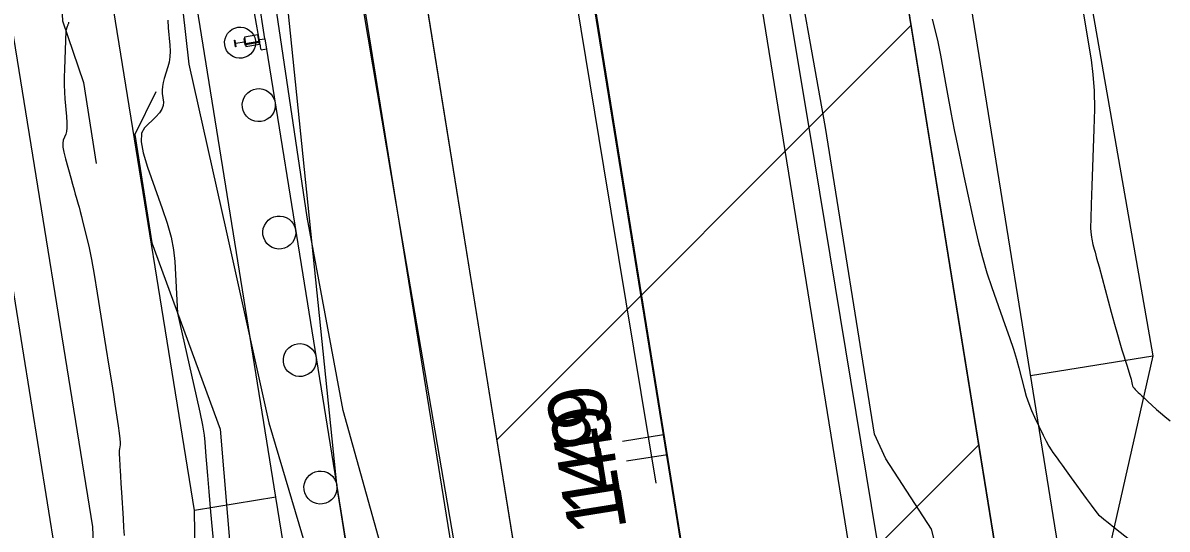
# Model space of a CAD drawing. Extents: x 2030588 to 2035216, y 462285 to 465007.
# Drawn here: x 2031209.2 to 2031264.6, y 464376.7 to 464401.2 of the extents above; entities that cross this region are included whole.
import ezdxf

# ---------------------------------------------------------------- set-up
doc = ezdxf.new("R2010")
doc.units = 0
for name, color, linetype in [('DT_P_Pavement_Surface', 7, 'Continuous'), ('DT_P_Slope_Break_Line', 7, 'Continuous'), ('DT_X_Contour_Minor', 7, 'Continuous'), ('GE_X_Alignment', 7, 'Continuous'), ('GE_X_Alignment_100_Stations', 7, 'Continuous'), ('MD_P_CONST_LIMITS', 7, 'Continuous'), ('MT_P_Temp_Road', 7, 'Continuous'), ('PV_P_EOP', 7, 'Continuous'), ('PV_P_Shoulder', 7, 'Continuous'), ('PV_X_COP', 7, 'Continuous'), ('PV_X_EOP', 7, 'Continuous'), ('PV_X_Shoulder_Aggregate', 7, 'Continuous'), ('RD_P_GR_Lt', 7, 'Continuous'), ('RD_P_GR_Rt', 7, 'Continuous'), ('RW_X_CL', 7, 'Continuous'), ('RW_X_CL_100_Stations', 7, 'Continuous'), ('RW_X_Esmt_SH', 7, 'Continuous'), ('SV_X_Break_Lines', 7, 'Continuous')]:
    doc.layers.add(name, color=color, linetype=linetype)

msp = doc.modelspace()

# ---------------------------------------------------------------- linework, layer by layer
at = {"layer": 'DT_P_Pavement_Surface'}
for p, q in [((2031232.105, 464381.011), (2031252.165, 464401.071)), ((2031235.377, 464360.715), (2031255.437, 464380.775))]:
    msp.add_line(p, q, dxfattribs=at)
msp.add_lwpolyline([(2031217.338, 464453.535), (2031220.901, 464430.815), (2031223.994, 464431.313), (2031239.433, 464335.56), (2031275.613, 464341.393), (2031280.179, 464344.377), (2031288.444, 464349.459), (2031281.782, 464364.953), (2031278.976, 464364.399), (2031274.659, 464363.749), (2031271.761, 464363.269), (2031268.389, 464363.667), (2031266.116, 464364.094), (2031263.849, 464365.29), (2031262.287, 464366.863), (2031259.966, 464369.755), (2031257.582, 464371.903), (2031256.7, 464372.941), (2031246.698, 464434.974), (2031241.124, 464434.075), (2031240.612, 464437.401)], dxfattribs=at)
at = {"layer": 'DT_P_Slope_Break_Line'}
for p, q in [((2031221.412, 464378.231), (2031213.454, 464427.588)), ((2031259.564, 464409.702), (2031263.859, 464385.074)), ((2031253.957, 464408.798), (2031260.316, 464369.36)), ((2031217.463, 464377.594), (2031213.484, 464402.273)), ((2031257.936, 464384.119), (2031263.859, 464385.074)), ((2031263.859, 464385.074), (2031260.316, 464369.36)), ((2031221.412, 464378.231), (2031217.463, 464377.594)), ((2031234.941, 464294.323), (2031221.412, 464378.231)), ((2031217.918, 464352.347), (2031217.463, 464377.594))]:
    msp.add_line(p, q, dxfattribs=at)
at = {"layer": 'DT_X_Contour_Minor'}
for points in [[(2031260.454, 464401.918), (2031260.587, 464401.133), (2031260.876, 464399.394), (2031260.966, 464398.695), (2031261.019, 464397.903), (2031261.036, 464397.017), (2031261.015, 464396.039), (2031260.912, 464393.304), (2031260.88, 464392.395), (2031260.86, 464391.719), (2031260.853, 464391.276), (2031260.859, 464391.067), (2031260.89, 464390.818), (2031260.903, 464390.726), (2031260.919, 464390.636), (2031260.939, 464390.549), (2031260.961, 464390.463), (2031261.025, 464390.238), (2031261.067, 464390.087), (2031261.144, 464389.802), (2031261.258, 464389.385), (2031261.407, 464388.835), (2031261.852, 464387.189), (2031262.009, 464386.612), (2031262.148, 464386.115), (2031262.269, 464385.698), (2031262.371, 464385.361), (2031262.619, 464384.569), (2031262.702, 464384.301), (2031262.765, 464384.092), (2031262.808, 464383.942), (2031262.831, 464383.85), (2031262.867, 464383.684), (2031262.886, 464383.623), (2031262.915, 464383.563), (2031262.956, 464383.504), (2031263.008, 464383.448), (2031263.161, 464383.299), (2031263.231, 464383.231), (2031263.329, 464383.139), (2031263.454, 464383.023), (2031263.605, 464382.884), (2031264.045, 464382.479), (2031264.228, 464382.318), (2031264.447, 464382.137), (2031264.701, 464381.937)], [(2031216.172, 464401.327), (2031216.2, 464400.948), (2031216.27, 464400.114), (2031216.284, 464399.814), (2031216.275, 464399.539), (2031216.242, 464399.29), (2031216.186, 464399.066), (2031216.005, 464398.503), (2031215.948, 464398.299), (2031215.913, 464398.109), (2031215.9, 464397.932), (2031215.909, 464397.77), (2031215.962, 464397.354), (2031215.954, 464397.193), (2031215.89, 464397.021), (2031215.771, 464396.838), (2031215.595, 464396.644), (2031215.053, 464396.113), (2031214.909, 464395.845), (2031214.884, 464395.439), (2031214.977, 464394.896), (2031215.188, 464394.214), (2031215.911, 464392.214), (2031216.152, 464391.49), (2031216.332, 464390.82), (2031216.452, 464390.203), (2031216.512, 464389.64), (2031216.651, 464387.137), (2031217.557, 464383.136), (2031217.729, 464382.353), (2031217.856, 464381.72), (2031217.939, 464381.237), (2031217.977, 464380.903), (2031218.018, 464380.211), (2031218.044, 464379.848), (2031218.092, 464379.279), (2031218.161, 464378.504), (2031218.252, 464377.522), (2031218.525, 464374.629)], [(2031253.186, 464401.365), (2031253.433, 464400.347), (2031253.584, 464399.625), (2031253.855, 464398.094), (2031253.949, 464397.564), (2031254.029, 464397.124), (2031254.094, 464396.774), (2031254.145, 464396.514), (2031254.261, 464395.938), (2031254.322, 464395.641), (2031254.419, 464395.182), (2031254.551, 464394.56), (2031254.719, 464393.775), (2031255.213, 464391.466), (2031255.405, 464390.624), (2031255.611, 464389.831), (2031255.83, 464389.086), (2031256.063, 464388.39), (2031256.703, 464386.599), (2031256.925, 464385.964), (2031257.111, 464385.403), (2031257.261, 464384.915), (2031257.376, 464384.502), (2031257.633, 464383.498), (2031257.737, 464383.128), (2031257.856, 464382.772), (2031257.99, 464382.43), (2031258.14, 464382.102), (2031258.559, 464381.244), (2031258.705, 464380.95), (2031258.832, 464380.71), (2031258.938, 464380.525), (2031259.024, 464380.395), (2031259.226, 464380.122), (2031259.326, 464379.986), (2031259.474, 464379.782), (2031259.671, 464379.51), (2031259.917, 464379.171), (2031260.636, 464378.177), (2031260.875, 464377.848), (2031261.054, 464377.608), (2031261.171, 464377.455), (2031261.227, 464377.39), (2031261.295, 464377.334), (2031261.357, 464377.285), (2031261.491, 464377.178), (2031261.698, 464377.014), (2031261.978, 464376.793), (2031262.82, 464376.127)], [(2031211.365, 464401.228), (2031211.365, 464401.187), (2031211.362, 464401.163), (2031211.349, 464401.124), (2031211.343, 464401.105), (2031211.335, 464401.08), (2031211.324, 464401.047), (2031211.311, 464401.008), (2031211.243, 464400.807), (2031211.169, 464398.945), (2031211.158, 464398.556), (2031211.158, 464398.186), (2031211.17, 464397.836), (2031211.192, 464397.506), (2031211.266, 464396.651), (2031211.284, 464396.358), (2031211.285, 464396.117), (2031211.268, 464395.93), (2031211.233, 464395.797), (2031211.116, 464395.512), (2031211.089, 464395.376), (2031211.098, 464395.18), (2031211.142, 464394.926), (2031211.22, 464394.611), (2031211.478, 464393.695), (2031211.567, 464393.378), (2031211.64, 464393.116), (2031211.699, 464392.908), (2031211.743, 464392.754), (2031211.838, 464392.415), (2031211.88, 464392.265), (2031211.932, 464392.068), (2031211.995, 464391.825), (2031212.069, 464391.535), (2031212.28, 464390.701), (2031212.369, 464390.304), (2031212.478, 464389.74), (2031212.608, 464389.007), (2031212.757, 464388.108), (2031213.182, 464385.485), (2031213.329, 464384.575), (2031213.451, 464383.813), (2031213.547, 464383.2), (2031213.617, 464382.734), (2031213.771, 464381.69), (2031213.82, 464381.338), (2031213.852, 464381.068), (2031213.867, 464380.877), (2031213.864, 464380.768), (2031213.833, 464380.583), (2031213.824, 464380.503), (2031213.821, 464380.402), (2031213.824, 464380.279), (2031213.831, 464380.135), (2031213.86, 464379.723), (2031213.873, 464379.528), (2031213.89, 464379.255), (2031213.911, 464378.902), (2031213.936, 464378.47), (2031214.009, 464377.212), (2031214.036, 464376.769), (2031214.059, 464376.384)]]:
    msp.add_lwpolyline(points, dxfattribs=at)
at = {"layer": 'GE_X_Alignment'}
msp.add_line((2031257.417, 464274.275), (2031203.458, 464608.932), dxfattribs=at)
at = {"layer": 'GE_X_Alignment_100_Stations'}
msp.add_line((2031240.168, 464381.255), (2031238.193, 464380.936), dxfattribs=at)
at = {"layer": 'MD_P_CONST_LIMITS'}
msp.add_lwpolyline([(2031213.423, 464452.904), (2031204.569, 464426.156), (2031208.548, 464401.477), (2031212.527, 464376.798), (2031213.545, 464351.642), (2031212.78, 464331.262), (2031212.588, 464326.168), (2031200.6, 464313.585), (2031192.908, 464308.049), (2031189.455, 464298.429), (2031209.379, 464281.464), (2031213.118, 464275.067), (2031222.806, 464250.019), (2031227.688, 464225.695), (2031242.004, 464202.354), (2031261.7, 464180.872), (2031268.395, 464156.387), (2031275.973, 464131.824), (2031285.052, 464107.55), (2031291.211, 464093.27), (2031304.871, 464099.462)], dxfattribs=at)
at = {"layer": 'MT_P_Temp_Road'}
for p, q in [((2031246.698, 464434.974), (2031262.137, 464339.22)), ((2031239.788, 464433.86), (2031255.227, 464338.106))]:
    msp.add_line(p, q, dxfattribs=at)
at = {"layer": 'PV_P_EOP'}
for p, q in [((2031223.994, 464431.313), (2031239.433, 464335.56)), ((2031221.032, 464430.836), (2031246.558, 464272.527))]:
    msp.add_line(p, q, dxfattribs=at)
at = {"layer": 'PV_P_Shoulder'}
for p, q in [((2031224.373, 464378.708), (2031219.058, 464430.518)), ((2031237.902, 464294.8), (2031224.373, 464378.708))]:
    msp.add_line(p, q, dxfattribs=at)
at = {"layer": 'PV_X_COP'}
msp.add_lwpolyline([(2031239.82, 464378.918), (2031237.293, 464394.23), (2031234.003, 464414.133), (2031230.523, 464435.72), (2031227.064, 464457.778), (2031223.868, 464479.049), (2031220.406, 464500.853), (2031217.211, 464522.279), (2031213.78, 464544.162), (2031210.249, 464566.426), (2031206.677, 464588.5), (2031203.458, 464608.932)], dxfattribs=at)
at = {"layer": 'PV_X_EOP'}
for points in [[(2031251.659, 464369.871), (2031250.509, 464376.276), (2031247.249, 464396.032), (2031243.946, 464415.746), (2031240.612, 464437.401), (2031237.044, 464459.528), (2031233.886, 464480.648), (2031230.49, 464502.512), (2031227.303, 464523.941), (2031223.954, 464545.798), (2031220.507, 464568.023), (2031216.931, 464590.234), (2031213.717, 464610.744)], [(2031295.06, 464096.69), (2031287.81, 464114.209), (2031281.552, 464131.387), (2031276.172, 464147.96), (2031272.883, 464159.049), (2031270.831, 464166.359), (2031266.261, 464184.745), (2031263.597, 464196.521), (2031261.604, 464205.334), (2031260.218, 464211.323), (2031255.622, 464233.278), (2031251.626, 464254.611), (2031248.06, 464273.969), (2031245.809, 464286.12), (2031244.042, 464295.612), (2031240.727, 464314.748), (2031237.529, 464334.128), (2031234.115, 464352.392), (2031233.443, 464356.077), (2031230.628, 464372.695), (2031227.228, 464392.461), (2031223.822, 464412.655), (2031220.382, 464434.076), (2031216.941, 464456.075)]]:
    msp.add_lwpolyline(points, dxfattribs=at)
at = {"layer": 'PV_X_Shoulder_Aggregate'}
for points in [[(2031255.511, 464233.314), (2031251.402, 464254.597), (2031247.773, 464274.033), (2031245.809, 464286.12), (2031244.042, 464295.612), (2031240.727, 464314.748), (2031237.529, 464334.128), (2031234.115, 464352.392), (2031233.443, 464356.077), (2031232.17, 464359.083), (2031229.545, 464365.856), (2031227.503, 464372.246), (2031224.664, 464382.428), (2031222.926, 464391.795), (2031219.919, 464412.021), (2031218.49, 464422.889), (2031218.4, 464433.793), (2031218.362, 464445.956)], [(2031277.635, 464237.84), (2031273.355, 464258.914), (2031270.066, 464278.166), (2031265.916, 464299.362), (2031263.298, 464318.606), (2031263.318, 464322.998), (2031263.199, 464325.189), (2031262.878, 464328.279), (2031260.848, 464338.194), (2031257.913, 464356.817), (2031254.754, 464370.404), (2031253.155, 464376.691), (2031250.944, 464380.086), (2031250.391, 464381.285), (2031248.022, 464396.129), (2031244.492, 464415.82), (2031241.204, 464437.394)]]:
    msp.add_lwpolyline(points, dxfattribs=at)
at = {"layer": 'RD_P_GR_Lt'}
for p, q in [((2031220.872, 464400.425), (2031216.823, 464426.893)), ((2031220.608, 464400.394), (2031215.814, 464426.739)), ((2031219.555, 464400.972), (2031219.555, 464400.972)), ((2031219.401, 464400.354), (2031219.419, 464400.357)), ((2031219.401, 464400.354), (2031219.419, 464400.357)), ((2031219.401, 464400.354), (2031219.401, 464400.354)), ((2031219.454, 464400.03), (2031219.401, 464400.354)), ((2031219.454, 464400.03), (2031219.401, 464400.354)), ((2031219.419, 464400.357), (2031219.419, 464400.357)), ((2031219.419, 464400.357), (2031219.439, 464400.231)), ((2031219.419, 464400.357), (2031219.439, 464400.231)), ((2031219.439, 464400.231), (2031219.439, 464400.231)), ((2031219.474, 464400.206), (2031219.873, 464400.271)), ((2031219.474, 464400.206), (2031219.873, 464400.271)), ((2031219.474, 464400.206), (2031219.474, 464400.206)), ((2031219.875, 464400.257), (2031219.476, 464400.192)), ((2031219.875, 464400.257), (2031219.476, 464400.192)), ((2031219.476, 464400.192), (2031219.476, 464400.192)), ((2031219.873, 464400.271), (2031219.873, 464400.271)), ((2031219.875, 464400.257), (2031219.875, 464400.257)), ((2031219.877, 464400.43), (2031219.895, 464400.433)), ((2031219.877, 464400.43), (2031219.895, 464400.433)), ((2031219.877, 464400.43), (2031219.877, 464400.43)), ((2031219.897, 464400.305), (2031219.877, 464400.43)), ((2031219.897, 464400.305), (2031219.877, 464400.43)), ((2031220.543, 464400.604), (2031219.885, 464400.497)), ((2031220.543, 464400.604), (2031219.885, 464400.497)), ((2031219.885, 464400.497), (2031219.885, 464400.497)), ((2031219.885, 464400.497), (2031219.957, 464400.045)), ((2031219.885, 464400.497), (2031219.957, 464400.045)), ((2031219.895, 464400.433), (2031219.895, 464400.433)), ((2031219.895, 464400.433), (2031219.947, 464400.109)), ((2031219.895, 464400.433), (2031219.947, 464400.109)), ((2031219.897, 464400.305), (2031219.897, 464400.305)), ((2031219.909, 464400.232), (2031219.909, 464400.232)), ((2031219.929, 464400.106), (2031219.909, 464400.232)), ((2031219.929, 464400.106), (2031219.909, 464400.232)), ((2031219.916, 464400.192), (2031219.933, 464400.195)), ((2031219.924, 464400.143), (2031219.916, 464400.192)), ((2031219.933, 464400.195), (2031220.591, 464400.301)), ((2031219.941, 464400.146), (2031219.933, 464400.195)), ((2031219.941, 464400.146), (2031219.933, 464400.195)), ((2031219.937, 464400.17), (2031220.595, 464400.276)), ((2031219.937, 464400.17), (2031220.595, 464400.276)), ((2031219.941, 464400.146), (2031220.599, 464400.252)), ((2031220.415, 464400.351), (2031220.415, 464400.351)), ((2031220.543, 464400.604), (2031220.543, 464400.604)), ((2031220.616, 464400.151), (2031220.543, 464400.604)), ((2031220.616, 464400.151), (2031220.543, 464400.604)), ((2031220.599, 464400.252), (2031220.591, 464400.301)), ((2031220.609, 464400.381), (2031220.872, 464400.423)), ((2031220.872, 464400.425), (2031222.861, 464388.085)), ((2031218.934, 464400.112), (2031218.934, 464400.112)), ((2031219.44, 464400.115), (2031219.457, 464400.118)), ((2031219.448, 464400.066), (2031219.44, 464400.115)), ((2031219.444, 464400.09), (2031219.461, 464400.093)), ((2031219.444, 464400.09), (2031219.461, 464400.093)), ((2031219.448, 464400.066), (2031219.465, 464400.069)), ((2031219.451, 464400.158), (2031219.451, 464400.158)), ((2031219.451, 464400.158), (2031219.471, 464400.032)), ((2031219.451, 464400.158), (2031219.471, 464400.032)), ((2031219.471, 464400.032), (2031219.454, 464400.03)), ((2031219.471, 464400.032), (2031219.454, 464400.03)), ((2031219.454, 464400.03), (2031219.454, 464400.03)), ((2031219.465, 464400.069), (2031219.457, 464400.118)), ((2031219.471, 464400.032), (2031219.471, 464400.032)), ((2031219.92, 464400.167), (2031219.937, 464400.17)), ((2031219.92, 464400.167), (2031219.937, 464400.17)), ((2031219.924, 464400.143), (2031219.941, 464400.146)), ((2031219.947, 464400.109), (2031219.929, 464400.106)), ((2031219.947, 464400.109), (2031219.929, 464400.106)), ((2031219.929, 464400.106), (2031219.929, 464400.106)), ((2031219.947, 464400.109), (2031219.947, 464400.109)), ((2031219.957, 464400.045), (2031220.616, 464400.151)), ((2031219.957, 464400.045), (2031220.616, 464400.151)), ((2031219.957, 464400.045), (2031219.957, 464400.045)), ((2031220.616, 464400.151), (2031220.616, 464400.151)), ((2031220.693, 464399.888), (2031220.955, 464399.93)), ((2031219.794, 464399.491), (2031219.794, 464399.491)), ((2031222.861, 464388.085), (2031224.851, 464375.746))]:
    msp.add_line(p, q, dxfattribs=at)
for centre, major_axis in [((2031219.674, 464400.231), (-0.501, 0.558)), ((2031219.674, 464400.231), (-0.501, 0.558)), ((2031220.579, 464397.212), (0.534, -0.595)), ((2031221.574, 464391.043), (0.534, -0.595)), ((2031222.569, 464384.873), (0.534, -0.595)), ((2031223.564, 464378.703), (0.534, -0.595))]:
    msp.add_ellipse(centre, major_axis=major_axis, ratio=0.999987, dxfattribs=at)
for centre, major_axis, ratio, start_param, end_param in [((2031219.469, 464400.236), (0.0207, -0.0218), 0.999989, 4.112689, 5.683486), ((2031219.469, 464400.236), (0.0207, -0.0218), 0.999989, 4.112689, 5.683486), ((2031219.481, 464400.163), (-0.0182, 0.0239), 0.999989, 5.793153, 7.363949), ((2031219.481, 464400.163), (0.0182, -0.0239), 0.999989, 2.65156, 4.222356), ((2031219.868, 464400.3), (0.0204, -0.022), 0.999987, 5.696014, 7.266811), ((2031219.868, 464400.3), (0.0204, -0.022), 0.999987, 5.696014, 7.266811), ((2031219.88, 464400.227), (-0.0213, 0.0211), 0.99999, 4.081949, 5.652745), ((2031219.88, 464400.227), (0.0213, -0.0211), 0.99999, 0.940356, 2.511153)]:
    msp.add_ellipse(centre, major_axis=major_axis, ratio=ratio, start_param=start_param, end_param=end_param, dxfattribs=at)
msp.add_open_spline([(2031220.693, 464399.888), (2031220.672, 464400.009), (2031220.65, 464400.144), (2031220.627, 464400.278), (2031220.622, 464400.308), (2031220.619, 464400.325), (2031220.614, 464400.355), (2031220.612, 464400.368), (2031220.609, 464400.381)], degree=3, dxfattribs=at)
at = {"layer": 'RD_P_GR_Rt'}
msp.add_line((2031220.872, 464400.425), (2031220.955, 464399.93), dxfattribs=at)
at = {"layer": 'RW_X_CL'}
msp.add_line((2031264.454, 464230.531), (2031192.714, 464676.453), dxfattribs=at)
at = {"layer": 'RW_X_CL_100_Stations'}
msp.add_line((2031240.361, 464380.29), (2031238.386, 464379.973), dxfattribs=at)
at = {"layer": 'RW_X_Esmt_SH'}
msp.add_line((2031234.838, 464225.767), (2031163.098, 464671.689), dxfattribs=at)
at = {"layer": 'SV_X_Break_Lines'}
for points in [[(2031217.012, 464433.453), (2031216.32, 464420.833), (2031216.298, 464407.238), (2031217.203, 464399.185), (2031219, 464391.124), (2031221.062, 464381.837), (2031224.103, 464371.625), (2031228.129, 464363.197), (2031230.764, 464355.643), (2031232.084, 464351.471), (2031233.379, 464345.826), (2031234.299, 464339.736), (2031235.831, 464334.012)], [(2031207.578, 464430.162), (2031208.259, 464419.594), (2031210.817, 464406.149), (2031211.078, 464401.294), (2031212.094, 464398.302), (2031212.713, 464394.382)], [(2031215.592, 464397.852), (2031214.576, 464395.789), (2031215.4, 464390.543), (2031218.708, 464381.53), (2031219.597, 464370.968), (2031220.664, 464366.689)]]:
    msp.add_lwpolyline(points, dxfattribs=at)

# ---------------------------------------------------------------- texts
at = {"layer": 'GE_X_Alignment_100_Stations'}
msp.add_text('149', height=2.7997, rotation=99.1593, dxfattribs=at).set_placement((2031238.213, 464377.672))
at = {"layer": 'RW_X_CL_100_Stations'}
msp.add_text('149', height=2.7997, rotation=99.1395, dxfattribs=at).set_placement((2031238.405, 464376.709))

doc.saveas('drawing.dxf')
